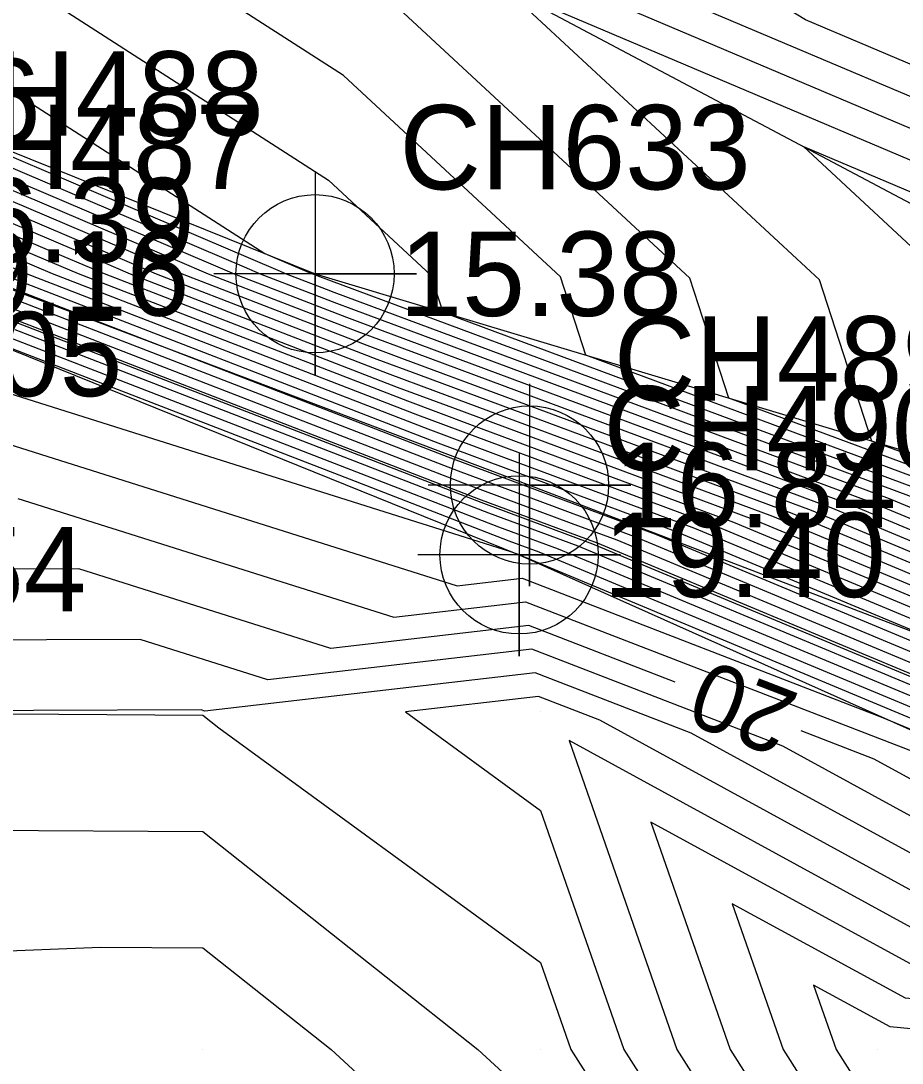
# Model space of a CAD drawing. Extents: x 2531902 to 2533249, y 715219 to 716099.
# Drawn here: x 2532894.6 to 2532920.72, y 715589.6 to 715620.47 of the extents above; entities that cross this region are included whole.
import ezdxf

# ---------------------------------------------------------------- set-up
doc = ezdxf.new("R2010")
doc.units = 0
for name, color, linetype in [('DTM Contours Major', 7, 'Continuous'), ('DTM Contours Major Text', 7, 'Continuous'), ('DTM Contours Minor', 7, 'Continuous'), ('Exist DTM Breakline', 7, 'Continuous'), ('Exist DTM Breakline Cogo Comment', 7, 'Continuous'), ('Exist DTM Breakline Cogo Elevation', 7, 'Continuous'), ('Exist DTM Breakline Cogo Number', 7, 'Continuous'), ('Exist DTM Breakline Cogo Point CELL', 7, 'Continuous'), ('Exist DTM Breakline Underwater', 7, 'Continuous'), ('Exist DTM Breakline Underwater Cogo Elevation', 7, 'Continuous'), ('Exist DTM Breakline Underwater Cogo Number', 7, 'Continuous'), ('Exist DTM Breakline Underwater Cogo Point CELL', 7, 'Continuous'), ('Exist DTM Drainline', 7, 'Continuous'), ('Exist DTM QL2 LIDAR Elevation Point', 7, 'Continuous'), ('Exist Hydro Stream or Body of Water', 7, 'Continuous'), ('Scratch_Level_2', 7, 'Continuous')]:
    doc.layers.add(name, color=color, linetype=linetype)

msp = doc.modelspace()

# ---------------------------------------------------------------- linework, layer by layer
at = {"layer": 'DTM Contours Major'}
for points in [[(2532890.655, 715638.312), (2532891.571, 715637.809), (2532905.569, 715626.076), (2532912.721, 715621.73), (2532926.519, 715615.888), (2532945.44, 715606.058), (2532953.026, 715604.623), (2532954.038, 715604.431), (2532959.139, 715598.483), (2532956.246, 715598.192), (2532949.44, 715599.203), (2532945.9, 715601.139), (2532940.376, 715602.093)], [(2532936.434, 715602.773), (2532934.742, 715603.065), (2532933.508, 715601.95), (2532924.263, 715605.674), (2532923.807, 715605.858), (2532922.059, 715606.587), (2532911.346, 715610.569), (2532910.592, 715612.891), (2532904.159, 715618.856), (2532896.829, 715623.571), (2532878.035, 715626.337), (2532856.052, 715634.14), (2532855.566, 715634.305)], [(2532855.365, 715626.975), (2532856.547, 715626.465), (2532863.083, 715623.817), (2532874.668, 715619.125), (2532883.316, 715615.518), (2532888.195, 715613.483), (2532889.358, 715612.987), (2532899.377, 715609.115), (2532908.761, 715605.487), (2532910.529, 715604.83), (2532915.888, 715602.595), (2532924.216, 715599.122), (2532926.388, 715598.246), (2532939.42, 715593.462), (2532944.107, 715591.741), (2532944.447, 715591.587), (2532948.208, 715589.876)], [(2532881.063, 715621.451), (2532900.228, 715613.278), (2532900.927, 715612.98), (2532904.255, 715611.694), (2532904.882, 715611.461), (2532919.177, 715606.148), (2532923.909, 715604.174), (2532925.144, 715603.677), (2532935.728, 715599.413), (2532939.197, 715598.139), (2532946.344, 715594.905), (2532946.607, 715594.786), (2532949.931, 715593.274), (2532971.696, 715584.677), (2532972.378, 715584.407), (2532973.68, 715583.807)], [(2532879.817, 715620.324), (2532881.521, 715619.613), (2532895.247, 715613.76), (2532897.071, 715612.983), (2532905.757, 715609.625), (2532907.394, 715609.016), (2532916.294, 715605.708), (2532924.012, 715602.49), (2532926.025, 715601.679), (2532932.615, 715599.024), (2532940.834, 715596.006), (2532945.284, 715593.993), (2532945.887, 715593.72), (2532953.507, 715590.253), (2532967.059, 715584.9), (2532969.618, 715583.889), (2532972.4, 715582.608)], [(2532877.78, 715619.5), (2532884.858, 715616.548), (2532890.265, 715614.243), (2532893.214, 715612.985), (2532907.259, 715607.556), (2532909.905, 715606.572), (2532913.412, 715605.269), (2532924.114, 715600.806), (2532926.906, 715599.681), (2532929.502, 715598.635), (2532942.47, 715593.874), (2532944.223, 715593.081), (2532945.167, 715592.654), (2532957.084, 715587.233), (2532962.422, 715585.124), (2532966.858, 715583.372), (2532970.35, 715581.763)], [(2532913.991, 715600.883), (2532909.652, 715602.559), (2532903.791, 715601.883), (2532896.326, 715604.236), (2532889.59, 715604.208), (2532886.085, 715600.293), (2532890, 715592.754), (2532896.968, 715593.032), (2532900, 715593.011), (2532903.799, 715590), (2532910, 715584.279), (2532912.219, 715580), (2532911.104, 715571.104), (2532920, 715573.9), (2532922.792, 715572.792), (2532930, 715571.991), (2532931.196, 715570), (2532932.414, 715568.221)], [(2532994.03, 715555.97), (2532996.996, 715560), (2532990.752, 715563.725), (2532989.952, 715564.108), (2532985.16, 715570.051), (2532970.453, 715576.899), (2532964.736, 715578.943), (2532963.003, 715576.997), (2532958.708, 715578.708), (2532955.803, 715580), (2532957.483, 715581.528), (2532947.518, 715585.016), (2532942.705, 715587.122), (2532940.418, 715590.138), (2532936.555, 715591.75), (2532925.398, 715596.429), (2532923.547, 715596.608), (2532919.889, 715598.604), (2532917.722, 715599.441)], [(2532957.968, 715560), (2532973.262, 715568.369), (2532972.222, 715570), (2532969.408, 715571.007), (2532969.212, 715570.788), (2532956.037, 715576.037), (2532950, 715578.722), (2532945.552, 715580), (2532940.791, 715582.083), (2532940, 715583.127), (2532932.731, 715590), (2532928.828, 715591.637), (2532921.27, 715592.366), (2532913.266, 715596.734), (2532915.617, 715590), (2532919.56, 715583.804)]]:
    msp.add_lwpolyline(points, dxfattribs=at)
at = {"layer": 'DTM Contours Minor'}
for points in [[(2532891.612, 715623.539), (2532903.717, 715615.754), (2532906.755, 715612.937), (2532907.111, 715611.841), (2532921.483, 715606.499), (2532923.828, 715605.521), (2532924.439, 715605.275), (2532936.842, 715600.278), (2532937.16, 715600.566), (2532940.041, 715600.069), (2532947.429, 715596.029), (2532961.632, 715593.918), (2532967.669, 715594.525), (2532957.024, 715606.939), (2532954.911, 715607.339), (2532939.08, 715610.334), (2532926.808, 715616.71), (2532917.858, 715620.5), (2532906.046, 715627.676), (2532897.202, 715635.09), (2532887.91, 715640.189)], [(2532887.473, 715639.673), (2532893.82, 715633.924), (2532905.092, 715624.475), (2532907.585, 715622.961), (2532926.231, 715615.065), (2532950.587, 715602.412), (2532932.324, 715605.565), (2532930.175, 715603.621), (2532924.087, 715606.074), (2532923.787, 715606.195), (2532922.636, 715606.675), (2532915.581, 715609.297), (2532914.43, 715612.845), (2532904.601, 715621.959), (2532902.046, 715623.602), (2532878.22, 715627.11), (2532859.428, 715633.78), (2532855.852, 715634.994)], [(2532877.517, 715623.291), (2532901.224, 715613.182), (2532901.698, 715612.98), (2532903.954, 715612.107), (2532904.38, 715611.949), (2532919.753, 715606.236), (2532923.889, 715604.511), (2532924.968, 715604.076), (2532936.351, 715599.49), (2532938.87, 715598.566), (2532946.556, 715595.088), (2532946.751, 715594.999), (2532949.216, 715593.878), (2532972.623, 715584.632)], [(2532886.395, 715623.508), (2532901.833, 715613.579), (2532903.217, 715612.989), (2532903.241, 715612.979), (2532903.354, 715612.935), (2532903.375, 715612.927), (2532920.906, 715606.411), (2532923.848, 715605.184), (2532924.616, 715604.875), (2532937.596, 715599.646), (2532938.215, 715599.419), (2532946.98, 715595.453), (2532947.039, 715595.426), (2532947.786, 715595.086), (2532958.272, 715590.944), (2532967.018, 715589.645), (2532974.992, 715590.446)], [(2532878.852, 715622.065), (2532899.232, 715613.375), (2532900.156, 715612.981), (2532904.555, 715611.28), (2532905.384, 715610.972), (2532918.6, 715606.06), (2532923.93, 715603.837), (2532925.32, 715603.277), (2532935.105, 715599.335), (2532939.525, 715597.713), (2532946.132, 715594.723), (2532946.463, 715594.573), (2532950.646, 715592.67), (2532970.768, 715584.721)], [(2532879.519, 715621.452), (2532898.235, 715613.471), (2532899.384, 715612.981), (2532904.856, 715610.866), (2532905.887, 715610.483), (2532918.024, 715605.972), (2532923.95, 715603.5), (2532925.496, 715602.877), (2532934.483, 715599.257), (2532939.852, 715597.286), (2532945.92, 715594.54), (2532946.319, 715594.36), (2532951.362, 715592.066), (2532969.841, 715584.766), (2532971.274, 715584.2)], [(2532908.95, 715621.438), (2532925.943, 715614.243), (2532941.784, 715606.013), (2532929.906, 715608.064), (2532926.841, 715605.293), (2532923.911, 715606.473), (2532923.766, 715606.532), (2532923.212, 715606.763), (2532919.817, 715608.025), (2532918.267, 715612.799), (2532908.95, 715621.438)], [(2532880.187, 715620.839), (2532897.239, 715613.567), (2532898.613, 715612.982), (2532905.156, 715610.452), (2532906.389, 715609.994), (2532917.447, 715605.884), (2532923.971, 715603.163), (2532925.673, 715602.478), (2532933.86, 715599.179), (2532940.179, 715596.859), (2532945.708, 715594.358), (2532946.175, 715594.146), (2532952.077, 715591.462), (2532968.913, 715584.811), (2532970.722, 715584.096)], [(2532880.854, 715620.226), (2532896.243, 715613.664), (2532897.842, 715612.982), (2532905.456, 715610.039), (2532906.891, 715609.505), (2532916.871, 715605.796), (2532923.991, 715602.827), (2532925.849, 715602.078), (2532933.237, 715599.102), (2532940.506, 715596.433), (2532945.496, 715594.175), (2532946.031, 715593.933), (2532952.792, 715590.858), (2532967.986, 715584.856), (2532970.17, 715583.993), (2532978.363, 715580.218)], [(2532887.721, 715619.268), (2532902.221, 715613.085), (2532902.469, 715612.979), (2532903.654, 715612.521), (2532903.877, 715612.438), (2532920.33, 715606.323), (2532923.869, 715604.848), (2532924.792, 715604.476), (2532936.973, 715599.568), (2532938.543, 715598.992), (2532946.768, 715595.27), (2532946.895, 715595.213), (2532948.501, 715594.482), (2532971.061, 715585.571)], [(2532923.876, 715607.297), (2532922.105, 715612.753), (2532917.795, 715616.749), (2532925.655, 715613.421), (2532932.981, 715609.614), (2532927.488, 715610.563), (2532923.876, 715607.297)], [(2532892.258, 715614.05), (2532894.757, 715612.984), (2532906.658, 715608.384), (2532908.901, 715607.55), (2532914.565, 715605.445), (2532924.073, 715601.479), (2532926.553, 715600.48), (2532930.747, 715598.791), (2532941.816, 715594.727), (2532944.647, 715593.446), (2532945.455, 715593.08), (2532955.653, 715588.441), (2532964.277, 715585.035), (2532967.962, 715583.579), (2532981.788, 715577.209)], [(2532893.254, 715613.953), (2532895.528, 715612.984), (2532906.358, 715608.797), (2532908.398, 715608.039), (2532915.141, 715605.533), (2532924.052, 715601.816), (2532926.377, 715600.88), (2532931.37, 715598.868), (2532941.488, 715595.153), (2532944.86, 715593.628), (2532945.599, 715593.293), (2532954.938, 715589.045), (2532965.204, 715584.99), (2532968.514, 715583.682), (2532980.932, 715577.962)], [(2532894.25, 715613.857), (2532896.299, 715612.983), (2532906.057, 715609.211), (2532907.896, 715608.528), (2532915.718, 715605.621), (2532924.032, 715602.153), (2532926.201, 715601.279), (2532931.992, 715598.946), (2532941.161, 715595.58), (2532945.072, 715593.81), (2532945.743, 715593.507), (2532954.223, 715589.649), (2532966.131, 715584.945), (2532969.066, 715583.786), (2532980.076, 715578.714)], [(2532890.901, 715612.986), (2532908.16, 715606.315), (2532911.412, 715605.106), (2532911.682, 715605.006), (2532924.175, 715599.795), (2532927.434, 715598.482), (2532927.634, 715598.402), (2532943.452, 715592.594), (2532943.587, 715592.533), (2532944.735, 715592.014), (2532959.229, 715585.421), (2532959.64, 715585.258), (2532965.202, 715583.061), (2532986.069, 715573.448)], [(2532891.672, 715612.986), (2532907.86, 715606.728), (2532910.91, 715605.595), (2532912.259, 715605.094), (2532924.155, 715600.132), (2532927.258, 715598.882), (2532928.256, 715598.48), (2532943.125, 715593.021), (2532943.799, 715592.716), (2532944.879, 715592.227), (2532958.514, 715586.025), (2532960.567, 715585.214), (2532965.754, 715583.165), (2532985.213, 715574.2)], [(2532892.443, 715612.985), (2532907.559, 715607.142), (2532910.408, 715606.084), (2532912.835, 715605.181), (2532924.134, 715600.469), (2532927.082, 715599.281), (2532928.879, 715598.557), (2532942.798, 715593.447), (2532944.011, 715592.898), (2532945.023, 715592.44), (2532957.799, 715586.629), (2532961.495, 715585.169), (2532966.306, 715583.268), (2532984.357, 715574.953)], [(2532893.986, 715612.984), (2532906.958, 715607.97), (2532909.403, 715607.061), (2532913.988, 715605.357), (2532924.093, 715601.143), (2532926.729, 715600.081), (2532930.124, 715598.713), (2532942.143, 715594.3), (2532944.435, 715593.263), (2532945.311, 715592.867), (2532956.368, 715587.837), (2532963.349, 715585.079), (2532967.41, 715583.475), (2532982.644, 715576.457)], [(2532892.005, 715611.666), (2532904.331, 715606.902), (2532909.061, 715605.073), (2532909.953, 715604.742), (2532918.373, 715601.23), (2532924.236, 715598.785), (2532925.766, 715598.169), (2532942.241, 715592.12), (2532944.088, 715591.349), (2532944.236, 715591.153), (2532944.55, 715591.016), (2532946.896, 715590.195), (2532961.375, 715583.608), (2532963.546, 715582.75), (2532971.692, 715578.998)], [(2532894.423, 715611.327), (2532908.46, 715605.901), (2532911.106, 715604.918), (2532913.402, 715603.96), (2532924.195, 715599.458), (2532927.011, 715598.324), (2532932.596, 715596.274), (2532943.78, 715592.168), (2532944.591, 715591.801), (2532954.836, 715587.14), (2532959.944, 715584.816), (2532964.65, 715582.957), (2532982.303, 715574.825)], [(2532890.893, 715610.5), (2532909.085, 715604.767), (2532909.285, 715604.689), (2532909.362, 715604.66), (2532909.376, 715604.654), (2532920.859, 715599.865), (2532924.257, 715598.448), (2532925.143, 715598.091), (2532934.691, 715594.585), (2532943.17, 715591.046), (2532943.854, 715590.145), (2532945.292, 715589.516), (2532956.061, 715585.747), (2532962.09, 715583.004), (2532962.994, 715582.647), (2532966.386, 715581.084), (2532989.493, 715570.439)], [(2532892.704, 715608.412), (2532907.529, 715603.74), (2532909.46, 715603.963), (2532920.139, 715599.837), (2532923.344, 715598.5), (2532924.277, 715598.111), (2532924.521, 715598.013), (2532927.142, 715597.051), (2532942.253, 715590.743), (2532943.471, 715589.137), (2532946.034, 715588.016), (2532961.959, 715582.442), (2532959.274, 715580), (2532959.777, 715579.777), (2532960.519, 715579.481), (2532962.868, 715582.118), (2532963.584, 715581.862), (2532988.872, 715570.087)], [(2532894.515, 715606.324), (2532905.66, 715602.811), (2532909.556, 715603.261), (2532922.6, 715598.222), (2532924.002, 715597.456), (2532924.711, 715597.388), (2532928.988, 715595.594), (2532941.335, 715590.441), (2532943.088, 715588.13), (2532946.776, 715586.516), (2532959.721, 715581.985), (2532957.539, 715580), (2532959.242, 715579.242), (2532961.761, 715578.239), (2532963.802, 715580.531), (2532967.019, 715579.38), (2532987.016, 715570.069)], [(2532973.887, 715574.417), (2532965.671, 715577.356), (2532964.245, 715575.755), (2532958.174, 715578.174), (2532954.068, 715580), (2532955.245, 715581.071), (2532948.261, 715583.516), (2532942.323, 715586.114), (2532940, 715589.176), (2532939.129, 715590), (2532926.084, 715595.471), (2532923.091, 715595.76), (2532917.178, 715598.987), (2532909.747, 715601.858), (2532901.922, 715600.955), (2532898.137, 715602.148), (2532889.794, 715602.113)], [(2532977.322, 715571.935), (2532966.605, 715575.769), (2532965.487, 715574.513), (2532957.639, 715577.639), (2532952.332, 715580), (2532953.007, 715580.614), (2532949.003, 715582.016), (2532941.94, 715585.107), (2532940, 715587.664), (2532937.529, 715590), (2532926.77, 715594.512), (2532922.636, 715594.911), (2532914.467, 715599.37), (2532909.843, 715601.156), (2532900.053, 715600.026), (2532899.948, 715600.06), (2532889.998, 715600.019)], [(2532922.181, 715594.063), (2532911.756, 715599.752), (2532909.938, 715600.454), (2532906, 715600), (2532910, 715597.084), (2532912.473, 715590), (2532916.802, 715583.198), (2532918.461, 715580), (2532918.241, 715578.241), (2532920, 715578.794), (2532926.296, 715576.296)], [(2532890.031, 715599.969), (2532900, 715599.902), (2532900.474, 715599.526), (2532910, 715592.582), (2532910.901, 715590), (2532912.479, 715587.521), (2532916.381, 715580), (2532915.862, 715575.862), (2532920, 715577.162), (2532925.128, 715575.128), (2532930, 715574.586), (2532932.755, 715570), (2532938.743, 715561.257), (2532938.576, 715560), (2532940, 715559.096), (2532945.73, 715555.73)], [(2532967.811, 715560), (2532978.405, 715565.797), (2532975.725, 715570), (2532968.473, 715572.594), (2532967.971, 715572.029), (2532956.571, 715576.571), (2532950, 715579.494), (2532948.238, 715580), (2532941.174, 715583.091), (2532940, 715584.639), (2532934.331, 715590), (2532928.142, 715592.595), (2532921.725, 715593.214), (2532910.851, 715599.149), (2532914.045, 715590), (2532920, 715580.643), (2532921.07, 715580), (2532927.464, 715577.464), (2532930, 715577.182), (2532934.313, 715570), (2532940, 715561.698), (2532944.519, 715560), (2532947.972, 715557.972)], [(2532893.5, 715596.5), (2532900, 715596.456), (2532908.146, 715590), (2532910, 715588.289), (2532914.3, 715580), (2532913.483, 715573.483), (2532920, 715575.531), (2532923.96, 715573.96), (2532930, 715573.289), (2532931.975, 715570), (2532936.27, 715563.73), (2532935.774, 715560), (2532940, 715557.317), (2532944.609, 715554.609)], [(2532940.409, 715581.076), (2532940, 715581.615), (2532931.132, 715590), (2532929.514, 715590.678), (2532920.815, 715591.518), (2532915.68, 715594.32), (2532917.188, 715590), (2532920, 715585.582), (2532929.293, 715580), (2532929.799, 715579.799), (2532930, 715579.777), (2532935.872, 715570), (2532940, 715563.973), (2532949.653, 715560.347), (2532950, 715560.182), (2532969.314, 715570), (2532955.502, 715575.502), (2532950, 715577.95), (2532942.867, 715580), (2532940.409, 715581.076)], [(2532920.359, 715590.669), (2532918.095, 715591.905), (2532918.76, 715590), (2532920, 715588.052), (2532924.879, 715585.121), (2532927.296, 715590), (2532920.359, 715590.669)]]:
    msp.add_lwpolyline(points, dxfattribs=at)
at = {"layer": 'Exist DTM Breakline'}
msp.add_lwpolyline([(2532713.668, 715632.91), (2532738.883, 715624.395), (2532759.246, 715620.539), (2532773.868, 715619.638), (2532797.122, 715620.541), (2532830.298, 715626.45), (2532834.772, 715629.357), (2532845.901, 715630.257), (2532852.301, 715627.724), (2532853.675, 715626.881), (2532873.942, 715617.949), (2532888.735, 715612.988), (2532909.367, 715604.653), (2532924.285, 715597.984), (2532944.343, 715591.433), (2532962.6, 715582.573), (2532991.856, 715569.195), (2533016.156, 715554.384)], dxfattribs=at)
at = {"layer": 'Exist DTM Breakline Cogo Point CELL'}
for points in [[(2532909.676, 715609.722), (2532909.676, 715603.722), (2532909.676, 715606.722), (2532912.676, 715606.722), (2532906.676, 715606.722)], [(2532909.367, 715607.653), (2532909.367, 715601.653), (2532909.367, 715604.653), (2532912.367, 715604.653), (2532906.367, 715604.653)]]:
    msp.add_lwpolyline(points, dxfattribs=at)
for centre in [(2532909.676, 715606.722), (2532909.367, 715604.653)]:
    msp.add_circle(centre, 2.344, dxfattribs=at)
at = {"layer": 'Exist DTM Breakline Underwater'}
msp.add_lwpolyline([(2532642.404, 715750.56), (2532658.799, 715717.787), (2532669.356, 715695.376), (2532679.885, 715666.767), (2532697.228, 715643.446), (2532713.346, 715638.817), (2532732.829, 715632.464), (2532756.843, 715626.148), (2532779.072, 715626.28), (2532796.688, 715625.652), (2532823.757, 715631.859), (2532837.11, 715635.289), (2532855.521, 715634.196), (2532877.341, 715623.453), (2532903.322, 715612.979), (2532923.748, 715606.844), (2532938.002, 715599.697), (2532947.164, 715595.611), (2532973.382, 715584.595), (2532998.348, 715572.794), (2533019.077, 715559.415)], dxfattribs=at)
at = {"layer": 'Exist DTM Breakline Underwater Cogo Point CELL'}
msp.add_lwpolyline([(2532903.322, 715615.979), (2532903.322, 715609.979), (2532903.322, 715612.979), (2532906.322, 715612.979), (2532900.322, 715612.979)], dxfattribs=at)
msp.add_circle((2532903.322, 715612.979), 2.344, dxfattribs=at)
at = {"layer": 'Exist DTM Drainline'}
msp.add_lwpolyline([(2532712.089, 715642.317), (2532734.218, 715637.287), (2532753.576, 715632.211), (2532781.659, 715633.208), (2532801.91, 715635.068), (2532816.971, 715637.962), (2532839.573, 715644.872), (2532859.48, 715643.736), (2532879.315, 715631.66), (2532904.837, 715623.619), (2532925.407, 715612.713), (2532951.291, 715602.124), (2532975.159, 715591.05), (2532999.274, 715579.213), (2533023.429, 715565.909)], dxfattribs=at)
at = {"layer": 'Exist DTM QL2 LIDAR Elevation Point'}
for p, q in [((2532900, 715600), (2532900, 715600)), ((2532910, 715600), (2532910, 715600)), ((2532900, 715590), (2532900, 715590)), ((2532910, 715590), (2532910, 715590)), ((2532920, 715590), (2532920, 715590))]:
    msp.add_line(p, q, dxfattribs=at)
at = {"layer": 'Exist Hydro Stream or Body of Water'}
msp.add_lwpolyline([(2532799.821, 715621.688), (2532825.866, 715627.44), (2532828.419, 715628.003), (2532832.005, 715633.511), (2532832.017, 715633.527), (2532835.552, 715631.335), (2532845.081, 715630.726), (2532846.796, 715630.623), (2532853.018, 715629.166), (2532854.009, 715628.204), (2532858.784, 715626.141), (2532874.956, 715619.591), (2532887.027, 715614.556), (2532890.708, 715612.987), (2532908.235, 715606.211), (2532911.538, 715604.984), (2532924.18, 715599.711), (2532927.478, 715598.382), (2532943.534, 715592.488), (2532944.699, 715591.96), (2532959.408, 715585.269), (2532965.064, 715583.035), (2532986.283, 715573.26)], dxfattribs=at)
at = {"layer": 'Scratch_Level_2'}
msp.add_lwpolyline([(2532714.664, 715634.736), (2532739.321, 715626.311), (2532759.871, 715623.13), (2532773.772, 715622.161), (2532797.407, 715622.564), (2532828.795, 715628.744), (2532834.22, 715630.983), (2532845.975, 715632.207), (2532853.028, 715629.31), (2532854.542, 715628.512), (2532875.028, 715620.214), (2532888.893, 715614.569), (2532909.676, 715606.722), (2532925.335, 715600.738), (2532945.352, 715592.461), (2532962.769, 715583.896), (2532993.283, 715570.726), (2533017.454, 715556.427)], dxfattribs=at)

# ---------------------------------------------------------------- texts
at = {"layer": 'DTM Contours Major Text'}
msp.add_text('20', height=2, rotation=158.876, dxfattribs=at).set_placement((2532917.737, 715600.508))
at = {"layer": 'Exist DTM Breakline Cogo Comment'}
msp.add_text('EL*4005', height=2.5, dxfattribs=at).set_placement((2532884.785, 715609.354))
at = {"layer": 'Exist DTM Breakline Cogo Elevation'}
for s, p in [('16.39', (2532891.393, 715613.319)), ('19.16', (2532891.235, 715611.738)), ('16.84', (2532912.176, 715605.472)), ('19.40', (2532911.867, 715603.403))]:
    msp.add_text(s, height=2.5, dxfattribs=at).set_placement(p)
at = {"layer": 'Exist DTM Breakline Cogo Number'}
for s, p in [('CH488', (2532891.393, 715617.069)), ('CH356', (2532884.785, 715616.854)), ('CH487', (2532891.235, 715615.488)), ('CH489', (2532912.176, 715609.222)), ('CH490', (2532911.867, 715607.153)), ('CH354', (2532886.138, 715602.977))]:
    msp.add_text(s, height=2.5, dxfattribs=at).set_placement(p)
at = {"layer": 'Exist DTM Breakline Underwater Cogo Elevation'}
msp.add_text('15.38', height=2.5, dxfattribs=at).set_placement((2532905.822, 715611.729))
at = {"layer": 'Exist DTM Breakline Underwater Cogo Number'}
msp.add_text('CH633', height=2.5, dxfattribs=at).set_placement((2532905.822, 715615.479))

doc.saveas('drawing.dxf')
